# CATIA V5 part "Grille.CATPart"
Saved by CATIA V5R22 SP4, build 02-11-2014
Part number: Grille
Material "ﾌﾟﾗｽﾃｨｯｸ": density 1200 kg/m3, Young's modulus 2.2e+09 Pa, Poisson ratio 0.38, thermal expansion 6.84e-05 1/K
Bounding box of the stored display mesh (mm): x -185 to -100.001, y -313 to 313, z 227 to 413
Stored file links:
  C:\DATA\Car_ASSY\教育モデル\5_ASM\Grille.CATPart
  C:\DATA\Car_ASSY\Car_Assy_1210\Grille_1210.CATPart
  C:\DATA\Car_ASSY\Car_Assy_1210\Grille.CATPart
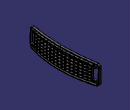
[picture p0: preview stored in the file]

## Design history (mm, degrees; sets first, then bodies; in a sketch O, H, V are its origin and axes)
Set1 "Front"
  Point1: (-1100, 0, 300)
  Circle1: type CtrRad, Start -30, End 30, Center Point1, Support xy-plane, Radius 1000, FirstDirection (1, 0, 0)
  Circle2: type CtrRad, Start 165, End 195, Center Point1, Support zx-plane, Radius 1000, FirstDirection (-1, 0, 0)
  Sweep1: type Unspec, Profile Circle2, Guide Circle1
Set2 "Danmen"
  Intersect1: ToIntersect1 Sweep1, ToIntersect2 Pad3
  Plane1: type Offset, RefPlane yz-plane, Offset 185, reversed
Body1 (main body)
  Body2
    Pad1: profile Intersect1, direction along X axis reversed, length 20
    Fillet1: radius 2, on face of Pad1
    Sketch1 on Plane1, origin (-185, 0, 0), H (0, 1, 0), V (0, 0, 1)
      circle A1 centre (280, 370) radius 9
      point P1 (280, 370)
      circle A2 centre (280, 370) radius 6
      circle A3 centre (280, 260) radius 9
      circle A4 centre (280, 260) radius 6
      circle A5 centre (-280, 370) radius 9
      circle A6 centre (-280, 370) radius 6
      circle A7 centre (-280, 260) radius 9
      circle A8 centre (-280, 260) radius 6
      radius A1 = 9
      radius A2 = 6
      distance H P1 = 370
      distance P1 V = 280
    Pad2: profile Sketch1, direction (1, 0, 0), up to the existing solid (limit type 2)
  Add1: tool Body2
Body3
  Sketch2 on yz-plane, origin (0, 0, 0), H (0, 1, 0), V (0, 0, 1)
    point P1 (0.0002, 410)
    construction line L1 (0.0002, 410) -> (310, 410)
    point P2 (310, 410)
    line L2 (310, 372.6426) -> (310, 250)
    point P3 (310, 230)
    line L3 (290, 230) -> (0, 230)
    point P4 (0, 230)
    circle A1 centre (280, 370) radius 8
    circle A2 centre (280, 260) radius 8
    spline S1 through (0.0002, 410) (184.2802, 403.8794) (310, 390)
    arc A3 centre (290, 250) radius 20 from (290, 230) to (310, 250) ccw
    point P5 (290, 230)
    point P6 (310, 250)
    arc A4 centre (290, 372.6426) radius 20 from (292.7155, 392.4574) to (310, 372.6426) cw
    point P8 (292.7155, 392.4574)
    point P9 (310, 372.6426)
    offsetcurve C1
    point P11 (0.0002, 390)
    point P12 (290.0001, 372.6425)
    construction line L4 (0.0002, 410) -> (0.0002, 390)
    point P13 (0.0002, 410)
    construction line L5 through (0.0002, 410) direction (-1, 0)
    construction line L6 (292.7155, 392.4574) -> (290.0001, 372.6425)
    construction line L7 through (292.7155, 392.4574) direction (0.9907, -0.1358)
    line L8 (260, 376.4843) -> (260, 255)
    point P14 (257.373, 372.6426)
    point P15 (257.373, 250)
    construction line L9 (310, 372.6426) -> (257.373, 372.6426)
    construction line L10 (310, 250) -> (257.373, 250)
    line L11 (255, 250) -> (0, 250)
    point P16 (290, 250)
    point P17 (0, 250)
    construction line L12 (290, 230) -> (290, 250)
    construction line L13 (0, 230) -> (0, 250)
    point P18 (260, 376.4843)
    point P19 (260, 250)
    line L14 (272, 370) -> (260, 370)
    point P20 (272, 370)
    point P21 (260, 370)
    line L15 (288, 370) -> (310, 370)
    point P22 (288, 370)
    point P23 (310, 370)
    line L16 (288, 260) -> (310, 260)
    point P24 (288, 260)
    point P25 (310, 260)
    line L17 (272, 260) -> (260, 260)
    point P26 (272, 260)
    point P27 (260, 260)
    line L18 (260, 275) -> (0, 275)
    point P28 (260, 275)
    point P29 (0, 275)
    construction line L19 (260, 250) -> (260, 275)
    construction line L20 (0, 250) -> (0, 275)
    line L21 (260, 300) -> (0, 300)
    point P30 (260, 300)
    point P31 (0, 300)
    construction line L22 (260, 275) -> (260, 300)
    construction line L23 (0, 275) -> (0, 300)
    line L24 (260, 325) -> (0, 325)
    point P32 (260, 325)
    point P33 (0, 325)
    construction line L25 (260, 300) -> (260, 325)
    construction line L26 (0, 300) -> (0, 325)
    line L27 (260, 350) -> (0, 350)
    point P34 (260, 350)
    point P35 (0, 350)
    construction line L28 (260, 325) -> (260, 350)
    construction line L29 (0, 325) -> (0, 350)
    line L30 (260, 375) -> (0, 375)
    point P36 (260, 375)
    point P37 (0, 375)
    construction line L31 (260, 350) -> (260, 375)
    construction line L32 (0, 350) -> (0, 375)
    arc A5 centre (255, 255) radius 5 from (260, 255) to (255, 250) cw
    point P38 (260, 255)
    point P39 (255, 250)
    line L33 (17.5, 250) -> (17.5, 389.9532)
    point P41 (17.5, 250)
    point P42 (17.5, 389.9532)
    line L34 (52.5, 250) -> (52.5, 389.5709)
    point P43 (52.5, 250)
    point P44 (52.5, 389.5709)
    line L35 (87.5, 250) -> (87.5, 388.769)
    point P45 (87.5, 250)
    point P46 (87.5, 388.769)
    line L36 (122.5, 250) -> (122.5, 387.4859)
    point P47 (122.5, 250)
    point P48 (122.5, 387.4859)
    line L37 (157.5, 250) -> (157.5, 385.6484)
    point P49 (157.5, 250)
    point P50 (157.5, 385.6484)
    line L38 (192.5, 250) -> (192.5, 383.1854)
    point P51 (192.5, 250)
    point P52 (192.5, 383.1854)
    line L39 (227.5, 250) -> (227.5, 380.0419)
    point P53 (227.5, 250)
    point P54 (227.5, 380.0419)
    point P55 (-0.0002, 410)
    point P56 (-310, 410)
    construction line L40 (-0.0002, 410) -> (-310, 410)
    point P57 (-310, 230)
    point P58 (0, 230)
    point P59 (-290, 230)
    point P60 (-310, 250)
    point P62 (-292.7155, 392.4574)
    point P63 (-310, 372.6426)
    point P65 (-0.0002, 390)
    point P66 (-290.0001, 372.6425)
    point P67 (-257.373, 372.6426)
    point P68 (-257.373, 250)
    point P69 (-290, 250)
    point P70 (0, 250)
    point P71 (-260, 376.4843)
    point P72 (-260, 250)
    point P73 (-272, 370)
    point P74 (-260, 370)
    point P75 (-288, 370)
    point P76 (-310, 370)
    point P77 (-288, 260)
    point P78 (-310, 260)
    point P79 (-272, 260)
    point P80 (-260, 260)
    point P81 (-260, 275)
    point P82 (0, 275)
    point P83 (-260, 300)
    point P84 (0, 300)
    point P85 (-260, 325)
    point P86 (0, 325)
    point P87 (-260, 350)
    point P88 (0, 350)
    point P89 (-260, 375)
    point P90 (0, 375)
    point P91 (-260, 255)
    point P92 (-255, 250)
    point P94 (-17.5, 250)
    point P95 (-17.5, 389.9532)
    point P96 (-52.5, 250)
    point P97 (-52.5, 389.5709)
    point P98 (-87.5, 250)
    point P99 (-87.5, 388.769)
    point P100 (-122.5, 250)
    point P101 (-122.5, 387.4859)
    point P102 (-157.5, 250)
    point P103 (-157.5, 385.6484)
    point P104 (-192.5, 250)
    point P105 (-192.5, 383.1854)
    point P106 (-227.5, 250)
    point P107 (-227.5, 380.0419)
    line L41 (-310, 372.6426) -> (-310, 250)
    line L42 (-290, 230) -> (0, 230)
    circle A6 centre (-280, 370) radius 8
    circle A7 centre (-280, 260) radius 8
    spline S2 through (-0.0002, 410) (-184.2802, 403.8794) (-310, 390)
    arc A8 centre (-290, 250) radius 20 from (-290, 230) to (-310, 250) cw
    arc A9 centre (-290, 372.6426) radius 20 from (-292.7155, 392.4574) to (-310, 372.6426) ccw
    offsetcurve C2
    line L43 (-260, 376.4843) -> (-260, 255)
    line L44 (-255, 250) -> (0, 250)
    line L45 (-272, 370) -> (-260, 370)
    line L46 (-288, 370) -> (-310, 370)
    line L47 (-288, 260) -> (-310, 260)
    line L48 (-272, 260) -> (-260, 260)
    line L49 (-260, 275) -> (0, 275)
    line L50 (-260, 300) -> (0, 300)
    line L51 (-260, 325) -> (0, 325)
    line L52 (-260, 350) -> (0, 350)
    line L53 (-260, 375) -> (0, 375)
    arc A10 centre (-255, 255) radius 5 from (-260, 255) to (-255, 250) ccw
    line L54 (-17.5, 250) -> (-17.5, 389.9532)
    line L55 (-52.5, 250) -> (-52.5, 389.5709)
    line L56 (-87.5, 250) -> (-87.5, 388.769)
    line L57 (-122.5, 250) -> (-122.5, 387.4859)
    line L58 (-157.5, 250) -> (-157.5, 385.6484)
    line L59 (-192.5, 250) -> (-192.5, 383.1854)
    line L60 (-227.5, 250) -> (-227.5, 380.0419)
    point P108 (0.0002, 410)
    point P109 (310, 390)
    point P110 (184.2802, 403.8794)
    point P111 (-0.0002, 410)
    point P112 (-310, 390)
    point P113 (-184.2802, 403.8794)
    distance H L3 = 230
    distance L2 V = 310
    distance P109 L1 = 20
    distance P2 P3 = 180
    distance V P110 = 184.2802
    distance P110 P109 V = 13.8794
    distance P108 P4 = 180
    radius A3 = 20
    radius A4 = 20
    distance L2 L8 = 50
    distance L3 L11 = 20
    distance L16 L3 = 30
    distance L15 L16 = 110
    distance A1 L15 = 8
    distance A1 L15 = 8
    distance A1 L2 = 38
    distance A2 L16 = 8
    distance A2 L16 = 8
    distance L2 A2 = 38
    distance L11 L18 = 25
    distance L18 L21 = 25
    distance L21 L24 = 25
    distance L24 L27 = 25
    distance L27 L30 = 25
    radius A5 = 5
    distance V L33 = 17.5
    distance L33 L34 = 35
    distance L34 L35 = 35
    distance L35 L36 = 35
    distance L36 L37 = 35
    distance L37 L38 = 35
    distance L38 L39 = 35
    horizontal: L1 H, L3 H, L14 H, L15 H, L16 H, L17 H
    vertical: L2 V, L33 V, L34 V, L35 V, L36 V, L37 V, L38 V, L39 V
    coincidence: P4 V, P108 P1, P109 L2, P2 L2, L3 P3, L2 P3, P108 P13, P12 C1, P16 L11, P20 A1, P21 L8, P22 L14, P22 A1, P23 L2, P24 A2, P25 L2, P26 L16, P26 A2, P27 L8, L8 P19, L11 P19, P41 L11, P42 C1, P43 L11, P44 C1, P45 L11, P46 C1, P47 L11, P48 C1, P49 L11, P50 C1, P51 L11, P52 C1, P53 L11, P54 C1, P4 P58, P17 P70, P29 P82, P31 P84, P33 P86, P35 P88, P37 P90
    tangency: A3 L3, A3 L2, A4 S1, A4 L2, L5 S1, L7 S1, A5 L8, A5 L11
    perpendicularity: L4 L5, L6 L7, L9 L2, L9 L8, L10 L2, L10 L8, L12 L3, L12 L11, L13 L3, L13 L11, L19 L11, L19 L18, L20 L11, L20 L18, L22 L18, L22 L21, L23 L18, L23 L21, L25 L21, L25 L24, L26 L21, L26 L24, L28 L24, L28 L27, L29 L24, L29 L27, L31 L27, L31 L30, L32 L27, L32 L30
    symmetry: P1 P55 V, P2 P56 V, L1 L40 V, P3 P57 V, P4 P58 V, P5 P59 V, P6 P60 V, P8 P62 V, P9 P63 V, P11 P65 V, P12 P66 V, P14 P67 V, P15 P68 V, P16 P69 V, P17 P70 V, P18 P71 V, P19 P72 V, P20 P73 V, P21 P74 V, P22 P75 V, P23 P76 V, P24 P77 V, P25 P78 V, P26 P79 V, P27 P80 V, P28 P81 V, P29 P82 V, P30 P83 V, P31 P84 V, P32 P85 V, P33 P86 V, P34 P87 V, P35 P88 V, P36 P89 V, P37 P90 V, P38 P91 V, P39 P92 V, P41 P94 V, P42 P95 V, P43 P96 V, P44 P97 V, P45 P98 V, P46 P99 V, P47 P100 V, P48 P101 V, P49 P102 V, P50 P103 V, P51 P104 V, P52 P105 V, P53 P106 V, P54 P107 V, L2 L41 V, L3 L42 V, A1 A6 V, A2 A7 V, S1 S2 V, A3 A8 V, A4 A9 V, C1 C2 V, L8 L43 V, L11 L44 V, L14 L45 V, L15 L46 V, L16 L47 V, L17 L48 V, L18 L49 V, L21 L50 V, L24 L51 V, L27 L52 V, L30 L53 V, A5 A10 V, L33 L54 V, L34 L55 V, L35 L56 V, L36 L57 V, L37 L58 V, L38 L59 V, L39 L60 V, P108 P111 V, P109 P112 V, P110 P113 V
  Pad3: profile Sketch2, direction (-1, 0, 0), length 350, thin wall 6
